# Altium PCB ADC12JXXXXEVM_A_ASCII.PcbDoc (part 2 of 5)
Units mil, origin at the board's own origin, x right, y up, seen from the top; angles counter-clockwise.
Board outline 5739 x 2680 mil, 10 copper layers (Top Layer L1, Gnd-Plane - L2, Signals - L3, Gnd-Plane - L4, Pwr Plane - L5, Signals - L6, Gnd-Plane - L7, Signals - L8, Gnd-Plane - L9, Bottom Layer - L10), stack 57.8 mil thick; 582 components, 343 nets, 1924 pads, 1318 vias.
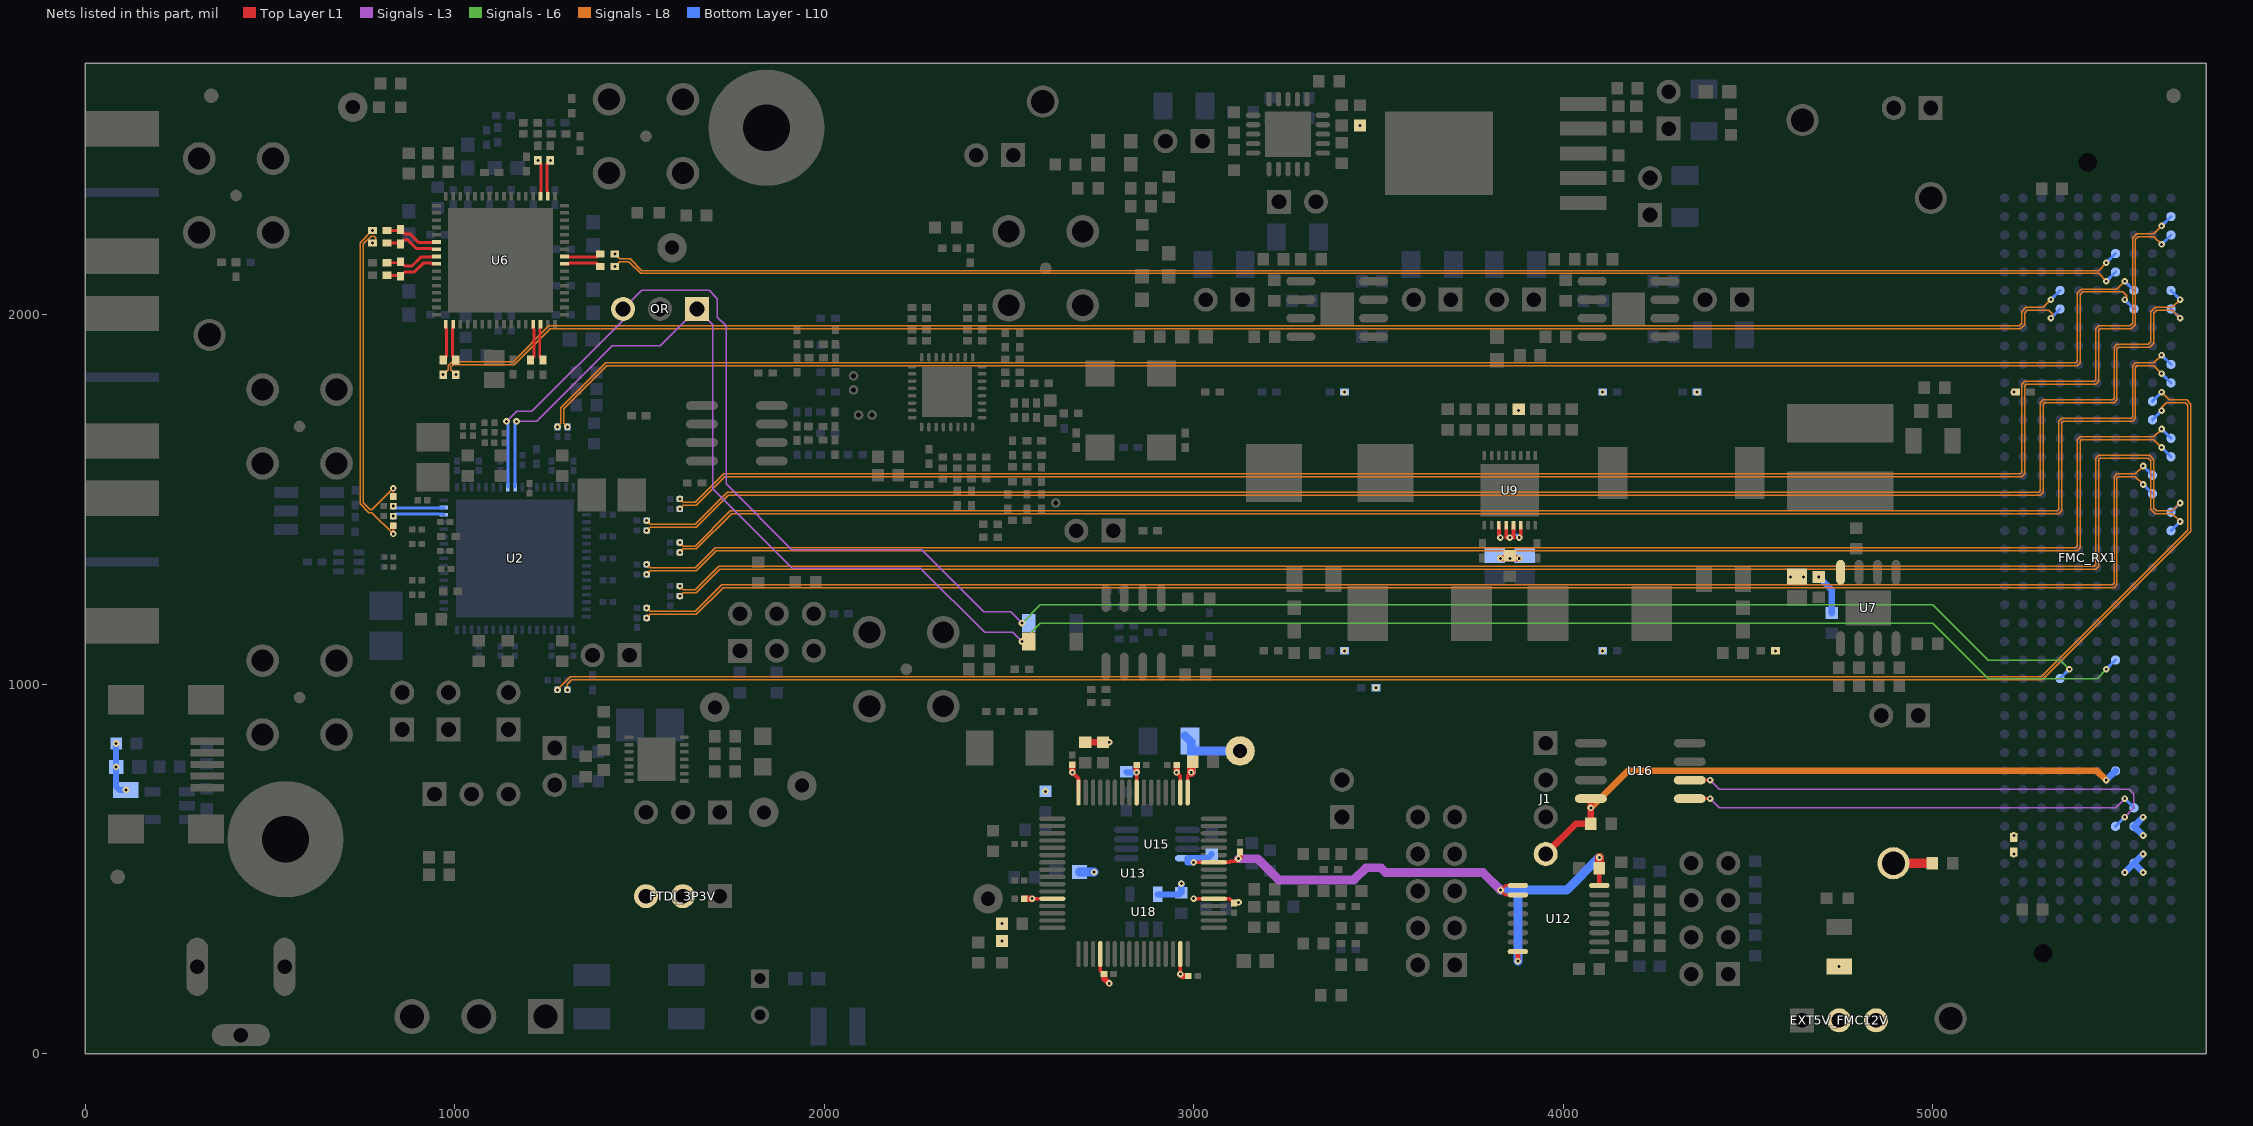
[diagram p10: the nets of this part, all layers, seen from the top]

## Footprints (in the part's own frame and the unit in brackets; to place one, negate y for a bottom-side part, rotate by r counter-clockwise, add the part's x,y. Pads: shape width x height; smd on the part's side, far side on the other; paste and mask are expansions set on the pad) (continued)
CONN_SEARAY_ASP-134488-01 [mm]
  round 0.635 hole 1.27 unplated mask+0.572: 401(27.191,0) 402(-27.191,-3.048)
  round 0.64 smd paste+0.125 mask+0.05: A1(24.716,5.715) A2(23.446,5.715) A3(22.176,5.715) A4(20.906,5.715) A5(19.636,5.715) A6(18.366,5.715) A7(17.096,5.715) A8(15.826,5.715) A9(14.556,5.715) A10(13.286,5.715) A11(12.016,5.715) A12(10.746,5.715) A13(9.476,5.715) A14(8.206,5.715) A15(6.936,5.715) A16(5.666,5.715) A17(4.396,5.715) A18(3.126,5.715) A19(1.856,5.715) A20(0.586,5.715) A21(-0.684,5.715) A22(-1.954,5.715) A23(-3.224,5.715) A24(-4.494,5.715) A25(-5.764,5.715) A26(-7.034,5.715) A27(-8.304,5.715) A28(-9.574,5.715) A29(-10.844,5.715) A30(-12.114,5.715) A31(-13.384,5.715) A32(-14.654,5.715) A33(-15.924,5.715) A34(-17.194,5.715) A35(-18.464,5.715) A36(-19.734,5.715) A37(-21.004,5.715) A38(-22.274,5.715) A39(-23.544,5.715) A40(-24.814,5.715) B1(24.716,4.445) B2(23.446,4.445) B3(22.176,4.445) B4(20.906,4.445) B5(19.636,4.445) B6(18.366,4.445) B7(17.096,4.445) B8(15.826,4.445) B9(14.556,4.445) B10(13.286,4.445) B11(12.016,4.445) B12(10.746,4.445) B13(9.476,4.445) B14(8.206,4.445) B15(6.936,4.445) B16(5.666,4.445) B17(4.396,4.445) B18(3.126,4.445) B19(1.856,4.445) B20(0.586,4.445) B21(-0.684,4.445) B22(-1.954,4.445) B23(-3.224,4.445) B24(-4.494,4.445) B25(-5.764,4.445) B26(-7.034,4.445) B27(-8.304,4.445) B28(-9.574,4.445) B29(-10.844,4.445) B30(-12.114,4.445) B31(-13.384,4.445) B32(-14.654,4.445) B33(-15.924,4.445) B34(-17.194,4.445) B35(-18.464,4.445) B36(-19.734,4.445) B37(-21.004,4.445) B38(-22.274,4.445) B39(-23.544,4.445) B40(-24.814,4.445) C1(24.716,3.175) C2(23.446,3.175) C3(22.176,3.175) C4(20.906,3.175) C5(19.636,3.175) C6(18.366,3.175) C7(17.096,3.175) C8(15.826,3.175) C9(14.556,3.175) C10(13.286,3.175) C11(12.016,3.175) C12(10.746,3.175) C13(9.476,3.175) C14(8.206,3.175) C15(6.936,3.175) C16(5.666,3.175) C17(4.396,3.175) C18(3.126,3.175) C19(1.856,3.175) C20(0.586,3.175) C21(-0.684,3.175) C22(-1.954,3.175) C23(-3.224,3.175) C24(-4.494,3.175) C25(-5.764,3.175) C26(-7.034,3.175) C27(-8.304,3.175) C28(-9.574,3.175) C29(-10.844,3.175) C30(-12.114,3.175) C31(-13.384,3.175) C32(-14.654,3.175) C33(-15.924,3.175) C34(-17.194,3.175) C35(-18.464,3.175) C36(-19.734,3.175) C37(-21.004,3.175) C38(-22.274,3.175) C39(-23.544,3.175) C40(-24.814,3.175) D1(24.716,1.905) D2(23.446,1.905) D3(22.176,1.905) D4(20.906,1.905) D5(19.636,1.905) D6(18.366,1.905) D7(17.096,1.905) D8(15.826,1.905) D9(14.556,1.905) D10(13.286,1.905) D11(12.016,1.905) D12(10.746,1.905) D13(9.476,1.905) D14(8.206,1.905) D15(6.936,1.905) D16(5.666,1.905) D17(4.396,1.905) D18(3.126,1.905) D19(1.856,1.905) D20(0.586,1.905) D21(-0.684,1.905) D22(-1.954,1.905) D23(-3.224,1.905) D24(-4.494,1.905) D25(-5.764,1.905) D26(-7.034,1.905) D27(-8.304,1.905) D28(-9.574,1.905) D29(-10.844,1.905) D30(-12.114,1.905) D31(-13.384,1.905) D32(-14.654,1.905) D33(-15.924,1.905) D34(-17.194,1.905) D35(-18.464,1.905) D36(-19.734,1.905) D37(-21.004,1.905) D38(-22.274,1.905) D39(-23.544,1.905) D40(-24.814,1.905) E1(24.716,0.635) E2(23.446,0.635) E3(22.176,0.635) E4(20.906,0.635) E5(19.636,0.635) E6(18.366,0.635) E7(17.096,0.635) E8(15.826,0.635) E9(14.556,0.635) E10(13.286,0.635) E11(12.016,0.635) E12(10.746,0.635) E13(9.476,0.635) E14(8.206,0.635) E15(6.936,0.635) E16(5.666,0.635) E17(4.396,0.635) E18(3.126,0.635) E19(1.856,0.635) E20(0.586,0.635) E21(-0.684,0.635) E22(-1.954,0.635) E23(-3.224,0.635) E24(-4.494,0.635) E25(-5.764,0.635) E26(-7.034,0.635) E27(-8.304,0.635) E28(-9.574,0.635) E29(-10.844,0.635) E30(-12.114,0.635) E31(-13.384,0.635) E32(-14.654,0.635) E33(-15.924,0.635) E34(-17.194,0.635) E35(-18.464,0.635) E36(-19.734,0.635) E37(-21.004,0.635) E38(-22.274,0.635) E39(-23.544,0.635) E40(-24.814,0.635) F1(24.716,-0.635) F2(23.446,-0.635) F3(22.176,-0.635) F4(20.906,-0.635) F5(19.636,-0.635) F6(18.366,-0.635) F7(17.096,-0.635) F8(15.826,-0.635) F9(14.556,-0.635) F10(13.286,-0.635) F11(12.016,-0.635) F12(10.746,-0.635) F13(9.476,-0.635) F14(8.206,-0.635) F15(6.936,-0.635) F16(5.666,-0.635) F17(4.396,-0.635) F18(3.126,-0.635) F19(1.856,-0.635) F20(0.586,-0.635) F21(-0.684,-0.635) F22(-1.954,-0.635) F23(-3.224,-0.635) F24(-4.494,-0.635) F25(-5.764,-0.635) F26(-7.034,-0.635) F27(-8.304,-0.635) F28(-9.574,-0.635) F29(-10.844,-0.635) F30(-12.114,-0.635) F31(-13.384,-0.635) F32(-14.654,-0.635) F33(-15.924,-0.635) F34(-17.194,-0.635) F35(-18.464,-0.635) F36(-19.734,-0.635) F37(-21.004,-0.635) F38(-22.274,-0.635) F39(-23.544,-0.635) F40(-24.814,-0.635) G1(24.716,-1.905) G2(23.446,-1.905) G3(22.176,-1.905) G4(20.906,-1.905) G5(19.636,-1.905) G6(18.366,-1.905) G7(17.096,-1.905) G8(15.826,-1.905) G9(14.556,-1.905) G10(13.286,-1.905) G11(12.016,-1.905) G12(10.746,-1.905) G13(9.476,-1.905) G14(8.206,-1.905) G15(6.936,-1.905) G16(5.666,-1.905) G17(4.396,-1.905) G18(3.126,-1.905) G19(1.856,-1.905) G20(0.586,-1.905) G21(-0.684,-1.905) G22(-1.954,-1.905) G23(-3.224,-1.905) G24(-4.494,-1.905) G25(-5.764,-1.905) G26(-7.034,-1.905) G27(-8.304,-1.905) G28(-9.574,-1.905) G29(-10.844,-1.905) G30(-12.114,-1.905) G31(-13.384,-1.905) G32(-14.654,-1.905) G33(-15.924,-1.905) G34(-17.194,-1.905) G35(-18.464,-1.905) G36(-19.734,-1.905) G37(-21.004,-1.905) G38(-22.274,-1.905) G39(-23.544,-1.905) G40(-24.814,-1.905) H1(24.716,-3.175) H2(23.446,-3.175) H3(22.176,-3.175) H4(20.906,-3.175) H5(19.636,-3.175) H6(18.366,-3.175) H7(17.096,-3.175) H8(15.826,-3.175) H9(14.556,-3.175) H10(13.286,-3.175) H11(12.016,-3.175) H12(10.746,-3.175) H13(9.476,-3.175) H14(8.206,-3.175) H15(6.936,-3.175) H16(5.666,-3.175) H17(4.396,-3.175) H18(3.126,-3.175) H19(1.856,-3.175) H20(0.586,-3.175) H21(-0.684,-3.175) H22(-1.954,-3.175) H23(-3.224,-3.175) H24(-4.494,-3.175) H25(-5.764,-3.175) H26(-7.034,-3.175) H27(-8.304,-3.175) H28(-9.574,-3.175) H29(-10.844,-3.175) H30(-12.114,-3.175) H31(-13.384,-3.175) H32(-14.654,-3.175) H33(-15.924,-3.175) H34(-17.194,-3.175) H35(-18.464,-3.175) H36(-19.734,-3.175) H37(-21.004,-3.175) H38(-22.274,-3.175) H39(-23.544,-3.175) H40(-24.814,-3.175) J1(24.716,-4.445) J2(23.446,-4.445) J3(22.176,-4.445) J4(20.906,-4.445) J5(19.636,-4.445) J6(18.366,-4.445) J7(17.096,-4.445) J8(15.826,-4.445) J9(14.556,-4.445) J10(13.286,-4.445) J11(12.016,-4.445) J12(10.746,-4.445) J13(9.476,-4.445) J14(8.206,-4.445) J15(6.936,-4.445) J16(5.666,-4.445) J17(4.396,-4.445) J18(3.126,-4.445) J19(1.856,-4.445) J20(0.586,-4.445) J21(-0.684,-4.445) J22(-1.954,-4.445) J23(-3.224,-4.445) J24(-4.494,-4.445) J25(-5.764,-4.445) J26(-7.034,-4.445) J27(-8.304,-4.445) J28(-9.574,-4.445) J29(-10.844,-4.445) J30(-12.114,-4.445) J31(-13.384,-4.445) J32(-14.654,-4.445) J33(-15.924,-4.445) J34(-17.194,-4.445) J35(-18.464,-4.445) J36(-19.734,-4.445) J37(-21.004,-4.445) J38(-22.274,-4.445) J39(-23.544,-4.445) J40(-24.814,-4.445) K1(24.716,-5.715) K2(23.446,-5.715) K3(22.176,-5.715) K4(20.906,-5.715) K5(19.636,-5.715) K6(18.366,-5.715) K7(17.096,-5.715) K8(15.826,-5.715) K9(14.556,-5.715) K10(13.286,-5.715) K11(12.016,-5.715) K12(10.746,-5.715) K13(9.476,-5.715) K14(8.206,-5.715) K15(6.936,-5.715) K16(5.666,-5.715) K17(4.396,-5.715) K18(3.126,-5.715) K19(1.856,-5.715) K20(0.586,-5.715) K21(-0.684,-5.715) K22(-1.954,-5.715) K23(-3.224,-5.715) K24(-4.494,-5.715) K25(-5.764,-5.715) K26(-7.034,-5.715) K27(-8.304,-5.715) K28(-9.574,-5.715) K29(-10.844,-5.715) K30(-12.114,-5.715) K31(-13.384,-5.715) K32(-14.654,-5.715) K33(-15.924,-5.715) K34(-17.194,-5.715) K35(-18.464,-5.715) K36(-19.734,-5.715) K37(-21.004,-5.715) K38(-22.274,-5.715) K39(-23.544,-5.715) K40(-24.814,-5.715)
  silkscreen extent -28.49,-8.18 29.69,8.18, body extent -27.89,-7.34 29.49,7.34, height 7.07
CONN_USB-MINI-AB-651-305-142-821 [mm] "WE-USB2-MINI-AB TYPE"
  rect 0.5x2.3 smd: 1(-1.6,2.8) 2(-0.8,2.8) 3(0,2.8) 4(0.8,2.8) 5(1.6,2.8)
  rect 2x2.5 smd: 6(4.45,2.7) 7(4.45,-2.8) 8(-4.45,-2.8) 9(-4.45,2.7)
  silkscreen extent -4.03,-5.6 4,1.1, body extent -4.95,-5.72 4.95,3.68, height 4.12
DBV0005A_N [mm] "SOT23, 5-Leads, Body 2.9x1.6mm, Pitch 0.95mm, Lead Span 2.8mm, IPC Medium Density"
  rect 1.1x0.65 smd: 1(-1.2,0.95) 2(-1.2,0) 3(-1.2,-0.95) 4(1.2,-0.95) 5(1.2,0.95)
  silkscreen extent -1.33,-1.55 0.25,1.95, body extent -0.87,-1.52 0.87,1.53, height 1.45
DDA0008B_L [mm] "SOIC, 8-Leads, Body 4.9x3.9mm, Pitch 1.27mm, Exposed Pad, IPC High Density"
  oval 1.7x0.6 smd: 1(-2.45,1.905) 2(-2.45,0.635) 3(-2.45,-0.635) 4(-2.45,-1.905) 5(2.45,-1.905) 6(2.45,-0.635) 7(2.45,0.635) 8(2.45,1.905)
  rect 2.41x3.1 smd: 9(0,0)
  silkscreen extent -2.57,-2.5 1.2,2.88, body extent -2,-2.5 2,2.5, height 1.68
ESD_Overlay_Small [mil]
  silkscreen extent -62,-48 64,61
Fiducial10-30 [mm]
  round 1 smd paste-0.5 mask+1: 1(0,0)
  Keep-Out Layer circle w1.678: c0,0 r0.75
IND_TDK_ACM7060 [mm] "TDK Common Mode EMI Filter 7mmx6mm"
  rect 2.5x1.5 smd: 1(-3.25,1.5) 2(-3.25,-1.5) 3(3.25,-1.5) 4(3.25,1.5)
  silkscreen extent -4.8,-3.32 4.75,3.31, body extent -3.6,-3.12 3.6,3.07, height 3.55
Johnson_142-0701-80x [mil] "Johnson Components recommended land pattern"
  rect 25x200 smd: 1(0,0)
  rect 95x200 smd: 2(-172.5,0) 3(172.5,0)
  rect 95x200 smd far side: 4(-172.5,0) 5(172.5,0)
  silkscreen extent -235,-170 235,100, body extent -190,-92 190,480, height 165
Keystone5011 [mil] "Keystone Multipurpose loops"
  round 87 hole 63: 1(0,0)
  silkscreen extent -70,-70 70,70, body extent -63,-63 63,62, height 319
Keystone_1902C [mil] "Hex Standoff, 4-40 threaded, nylon"
  round 1 on Mech4: 0(0,0)
  body extent -145,-126 146,126, height 501
Label_650x200 [mil] "Thermal Transfer Label"
  silkscreen extent -325,-100 325,100, body extent -326,-101 326,101, height 1
LED_LTST-C170 [mm] "LITE-ON"
  rect 1.2x1.2 smd: 1(-1.05,0) 2(1.05,0)
  silkscreen extent -1.6,-1.1 3,1.1, body extent -1.05,-0.67 1.05,0.67, height 1.1
LED_LTST-C190 [mm] "Lite-On"
  rect 0.8x0.8 smd: 1(-0.75,0) 2(0.75,0)
  silkscreen extent -1.1,-0.8 1.8,0.8, body extent -0.85,-0.45 0.85,0.45, height 0.9
LQFP64_N [mm] "Thin QFP, 64-Leads, Body 10x10mm, Pitch 0.5mm, IPC Medium Density"
  oval 1.8x0.3 smd mask+0.049: 1(-5.55,3.75) 2(-5.55,3.25) 3(-5.55,2.75) 4(-5.55,2.25) 5(-5.55,1.75) 6(-5.55,1.25) 7(-5.55,0.75) 8(-5.55,0.25) 9(-5.55,-0.25) 10(-5.55,-0.75) 11(-5.55,-1.25) 12(-5.55,-1.75) 13(-5.55,-2.25) 14(-5.55,-2.75) 15(-5.55,-3.25) 16(-5.55,-3.75) 33(5.55,-3.75) 34(5.55,-3.25) 35(5.55,-2.75) 36(5.55,-2.25) 37(5.55,-1.75) 38(5.55,-1.25) 39(5.55,-0.75) 40(5.55,-0.25) 41(5.55,0.25) 42(5.55,0.75) 43(5.55,1.25) 44(5.55,1.75) 45(5.55,2.25) 46(5.55,2.75) 47(5.55,3.25) 48(5.55,3.75)
  oval 0.3x1.8 smd mask+0.049: 17(-3.75,-5.55) 18(-3.25,-5.55) 19(-2.75,-5.55) 20(-2.25,-5.55) 21(-1.75,-5.55) 22(-1.25,-5.55) 23(-0.75,-5.55) 24(-0.25,-5.55) 25(0.25,-5.55) 26(0.75,-5.55) 27(1.25,-5.55) 28(1.75,-5.55) 29(2.25,-5.55) 30(2.75,-5.55) 31(3.25,-5.55) 32(3.75,-5.55) 49(3.75,5.55) 50(3.25,5.55) 51(2.75,5.55) 52(2.25,5.55) 53(1.75,5.55) 54(1.25,5.55) 55(0.75,5.55) 56(0.25,5.55) 57(-0.25,5.55) 58(-0.75,5.55) 59(-1.25,5.55) 60(-1.75,5.55) 61(-2.25,5.55) 62(-2.75,5.55) 63(-3.25,5.55) 64(-3.75,5.55)
  silkscreen extent -5.67,-4.25 4.25,4.57, body extent -5,-5 5,5, height 1.6
M08A_L [mm] "SOIC, 8-Leads, Body 4.9x3.9mm, Pitch 1.27mm, IPC High Density"
  oval 1.9x0.6 smd: 1(-2.35,1.905) 2(-2.35,0.635) 3(-2.35,-0.635) 4(-2.35,-1.905) 5(2.35,-1.905) 6(2.35,-0.635) 7(2.35,0.635) 8(2.35,1.905)
  silkscreen extent -2.47,-2.5 1,2.88, body extent -2,-2.5 2,2.5, height 1.75
Mini-Circuits-DB1627 [mm] "Mini-Circuits DB1627 Footprint"
  rect 0.76x1.65 smd: 1(-1.27,1.59) 2(0,1.59) 3(1.27,1.59) 4(1.27,-1.59) 5(0,-1.59) 6(-1.27,-1.59)
  silkscreen extent -3.01,-2.03 1.91,2.03, body extent -1.91,-2.03 1.91,2.03, height 4.07
MRA08A_N [mm] "SOIC, 8-Leads, Body 4.9x3.9mm, Pitch 1.27mm, Exposed Pad, IPC Medium Density"
  oval 2x0.6 smd: 1(-2.5,1.905) 2(-2.5,0.635) 3(-2.5,-0.635) 4(-2.5,-1.905) 5(2.5,-1.905) 6(2.5,-0.635) 7(2.5,0.635) 8(2.5,1.905)
  rect 2.29x2.29 smd: 9(0,0)
  silkscreen extent -2.63,-2.5 1.1,2.88, body extent -2,-2.5 2,2.5, height 1.68
MSOP-MS8_N [mm] "TSOP, 8-Leads, Body 3x3mm, Pitch 0.65mm, IPC Medium Density"
  oval 1.7x0.45 smd mask+0.049: 1(-2.1,0.975) 2(-2.1,0.325) 3(-2.1,-0.325) 4(-2.1,-0.975) 5(2.1,-0.975) 6(2.1,-0.325) 7(2.1,0.325) 8(2.1,0.975)
  silkscreen extent -2.22,-1.55 0.85,1.87, body extent -1.6,-1.6 1.6,1.6, height 1.1
MSS1038 [mil]
  rect 80x140 smd: 1(-185,0) 2(185,0)
  silkscreen extent -216,-208 215,208, body extent -203,-201 203,201, height 158
NKD0064A [mm] "QFN, 64-Leads, Body 9x9mm, Pitch 0.5mm"
  rect 0.6x0.25 smd mask+0.051: 1(-4.4,3.75) 2(-4.4,3.25) 3(-4.4,2.75) 4(-4.4,2.25) 5(-4.4,1.75) 6(-4.4,1.25) 7(-4.4,0.75) 8(-4.4,0.25) 9(-4.4,-0.25) 10(-4.4,-0.75) 11(-4.4,-1.25) 12(-4.4,-1.75) 13(-4.4,-2.25) 14(-4.4,-2.75) 15(-4.4,-3.25) 16(-4.4,-3.75) 33(4.4,-3.75) 34(4.4,-3.25) 35(4.4,-2.75) 36(4.4,-2.25) 37(4.4,-1.75) 38(4.4,-1.25) 39(4.4,-0.75) 40(4.4,-0.25) 41(4.4,0.25) 42(4.4,0.75) 43(4.4,1.25) 44(4.4,1.75) 45(4.4,2.25) 46(4.4,2.75) 47(4.4,3.25) 48(4.4,3.75)
  rect 0.25x0.6 smd mask+0.051: 17(-3.75,-4.4) 18(-3.25,-4.4) 19(-2.75,-4.4) 20(-2.25,-4.4) 21(-1.75,-4.4) 22(-1.25,-4.4) 23(-0.75,-4.4) 24(-0.25,-4.4) 25(0.25,-4.4) 26(0.75,-4.4) 27(1.25,-4.4) 28(1.75,-4.4) 29(2.25,-4.4) 30(2.75,-4.4) 31(3.25,-4.4) 32(3.75,-4.4) 49(3.75,4.4) 50(3.25,4.4) 51(2.75,4.4) 52(2.25,4.4) 53(1.75,4.4) 54(1.25,4.4) 55(0.75,4.4) 56(0.25,4.4) 57(-0.25,4.4) 58(-0.75,4.4) 59(-1.25,4.4) 60(-1.75,4.4) 61(-2.25,4.4) 62(-2.75,4.4) 63(-3.25,4.4) 64(-3.75,4.4)
  rect 7.2x7.2 smd paste-3.6 mask+0.051: 65(0,0)
  silkscreen extent -5.52,-4.85 4.85,4.85, body extent -4.55,-4.55 4.55,4.55, height 0.8
"NY PMS 440 0025 PH"#1 [mm] "4-40 nylon screw and mounting hole"
  round 8 / inner round 4.216 / far side round 8 hole 3.2 mask+0.037: 1(0,0)
  body extent -3.3,-3.3 3.3,3.3, height 2.69
"NY PMS 440 0025 PH"#2 [mm] "4-40 nylon screw and mounting hole"
  round 8 / inner round 4.216 / far side round 8 hole 3.2: 1(0,0)
  body extent -3.3,-3.3 3.3,3.3, height 2.69
OSC_CWX [mm] "CONNOR WINFIELD"
  rect 2x1.8 smd: 1(-2.1,2.54) 2(-2.1,-2.54) 3(2.1,-2.54) 4(2.1,2.54)
  silkscreen extent -2.7,-3.7 2.7,4.55, body extent -2.65,-3.65 2.65,3.65, height 1.31
PBC03SAAN [mm] "Sullins 100mil, 1x3, 230 mil above insulator"
  rect 1.65x1.65 hole 1.016: 1(-2.54,0)
  round 1.65 hole 1.016: 2(0,0) 3(2.54,0)
  silkscreen extent -3.81,-1.27 3.81,1.27, body extent -3.81,-1.27 3.81,1.27, height 8.38
PW0016A_L [mm] "TSOP, 16-Leads, Body 5x4.4mm, Pitch 0.65mm, IPC High Density"
  oval 1.4x0.35 smd: 1(-2.8,2.275) 2(-2.8,1.625) 3(-2.8,0.975) 4(-2.8,0.325) 5(-2.8,-0.325) 6(-2.8,-0.975) 7(-2.8,-1.625) 8(-2.8,-2.275) 9(2.8,-2.275) 10(2.8,-1.625) 11(2.8,-0.975) 12(2.8,-0.325) 13(2.8,0.325) 14(2.8,0.975) 15(2.8,1.625) 16(2.8,2.275)
  silkscreen extent -2.92,-2.55 1.7,3.12, body extent -2.25,-2.55 2.25,2.55, height 1.2
RGW0020A [mm] "QFN, 20-Leads, Body 5x5mm, Pitch 0.65mm, Thermal Pad 3.15x3.15mm, TI Recommended"
  oval 1x0.35 smd paste-0.025 mask+0.07: 1(-2.4,1.3) 2(-2.4,0.65) 3(-2.4,0) 4(-2.4,-0.65) 5(-2.4,-1.3) 11(2.4,-1.3) 12(2.4,-0.65) 13(2.4,0) 14(2.4,0.65) 15(2.4,1.3)
  oval 0.35x1 smd paste-0.025 mask+0.07: 6(-1.3,-2.4) 7(-0.65,-2.4) 8(0,-2.4) 9(0.65,-2.4) 10(1.3,-2.4) 16(1.3,2.4) 17(0.65,2.4) 18(0,2.4) 19(-0.65,2.4) 20(-1.3,2.4)
  rect 3.15x3.15 smd paste-1.575 mask+0.07: 21(0,0)
  silkscreen extent -3.5,-2.73 2.73,2.73, body extent -2.58,-2.57 2.57,2.58, height 1
RHB0032E [mm] "QFN, 32-Leads, Body 5x5mm, Pitch 0.5mm, Thermal Pad 3.45x3.45mm, TI Recommended"
  oval 0.6x0.24 smd mask+0.07: 1(-2.4,1.75) 2(-2.4,1.25) 3(-2.4,0.75) 4(-2.4,0.25) 5(-2.4,-0.25) 6(-2.4,-0.75) 7(-2.4,-1.25) 8(-2.4,-1.75) 17(2.4,-1.75) 18(2.4,-1.25) 19(2.4,-0.75) 20(2.4,-0.25) 21(2.4,0.25) 22(2.4,0.75) 23(2.4,1.25) 24(2.4,1.75)
  oval 0.24x0.6 smd mask+0.07: 9(-1.75,-2.4) 10(-1.25,-2.4) 11(-0.75,-2.4) 12(-0.25,-2.4) 13(0.25,-2.4) 14(0.75,-2.4) 15(1.25,-2.4) 16(1.75,-2.4) 25(1.75,2.4) 26(1.25,2.4) 27(0.75,2.4) 28(0.25,2.4) 29(-0.25,2.4) 30(-0.75,2.4) 31(-1.25,2.4) 32(-1.75,2.4)
  rect 3.45x3.45 smd paste-1.725 mask+0.07: 33(0,0)
  silkscreen extent -2.72,2.29 -2.29,2.73, body extent -2.57,-2.57 2.58,2.58, height 1.01
RLY0068A [mm] "QFN, 68-Leads, Body 10x10mm, Pitch 0.5mm"
  rect 0.6x0.25 smd mask+0.051: 1(-4.9,4) 2(-4.9,3.5) 3(-4.9,3) 4(-4.9,2.5) 5(-4.9,2) 6(-4.9,1.5) 7(-4.9,1) 8(-4.9,0.5) 9(-4.9,0) 10(-4.9,-0.5) 11(-4.9,-1) 12(-4.9,-1.5) 13(-4.9,-2) 14(-4.9,-2.5) 15(-4.9,-3) 16(-4.9,-3.5) 17(-4.9,-4) 35(4.9,-4) 36(4.9,-3.5) 37(4.9,-3) 38(4.9,-2.5) 39(4.9,-2) 40(4.9,-1.5) 41(4.9,-1) 42(4.9,-0.5) 43(4.9,0) 44(4.9,0.5) 45(4.9,1) 46(4.9,1.5) 47(4.9,2) 48(4.9,2.5) 49(4.9,3) 50(4.9,3.5) 51(4.9,4)
  rect 0.25x0.6 smd mask+0.051: 18(-4,-4.9) 19(-3.5,-4.9) 20(-3,-4.9) 21(-2.5,-4.9) 22(-2,-4.9) 23(-1.5,-4.9) 24(-1,-4.9) 25(-0.5,-4.9) 26(0,-4.9) 27(0.5,-4.9) 28(1,-4.9) 29(1.5,-4.9) 30(2,-4.9) 31(2.5,-4.9) 32(3,-4.9) 33(3.5,-4.9) 34(4,-4.9) 52(4,4.9) 53(3.5,4.9) 54(3,4.9) 55(2.5,4.9) 56(2,4.9) 57(1.5,4.9) 58(1,4.9) 59(0.5,4.9) 60(0,4.9) 61(-0.5,4.9) 62(-1,4.9) 63(-1.5,4.9) 64(-2,4.9) 65(-2.5,4.9) 66(-3,4.9) 67(-3.5,4.9) 68(-4,4.9)
  rect 8.1x8.1 smd paste-4.05 mask+0.051: 69(0,0)
  silkscreen extent -5.87,-5.2 5.2,5.2, body extent -5.05,-5.05 5.05,5.05, height 1.01
SDA14B [mm] "SON, 14-Leads, Body 4x4mm, Pitch 0.5mm, NSC Recommended"
  rect 0.6x0.25 smd paste-0.125 mask+0.051: 1(-1.9,1.5) 2(-1.9,1) 3(-1.9,0.5) 4(-1.9,0) 5(-1.9,-0.5) 6(-1.9,-1) 7(-1.9,-1.5) 8(1.9,-1.5) 9(1.9,-1) 10(1.9,-0.5) 11(1.9,0) 12(1.9,0.5) 13(1.9,1) 14(1.9,1.5)
  rect 2.6x3 smd paste-1.3 mask+0.051: 15(0,0)
  silkscreen extent -2.82,-2.2 2.35,2.87, body extent -2.05,-2.05 2.05,2.05, height 0.8
SDA16A [mm] "SON, 16-Leads, Body 5x5mm, Pitch 0.5mm, NSC Recommended"
  rect 0.6x0.25 smd paste-0.125 mask+0.051: 1(-2.4,1.75) 2(-2.4,1.25) 3(-2.4,0.75) 4(-2.4,0.25) 5(-2.4,-0.25) 6(-2.4,-0.75) 7(-2.4,-1.25) 8(-2.4,-1.75) 9(2.4,-1.75) 10(2.4,-1.25) 11(2.4,-0.75) 12(2.4,-0.25) 13(2.4,0.25) 14(2.4,0.75) 15(2.4,1.25) 16(2.4,1.75)
  rect 3.6x4 smd paste-1.8 mask+0.051: 17(0,0)
  silkscreen extent -2.85,-2.7 2.85,3.53, body extent -2.55,-2.55 2.55,2.55, height 0.8
SMC [mil] "Molded Diode, 2-Leads, Body 6.9x5.8mm, IPC Medium Density, based on OnSemi component dimensions and land patterns"
  rect 110x150 smd: 1(-140.49,0) 2(140.49,0)
  silkscreen extent -221,-124 189,124, body extent -156,-116 156,116, height 91
SNT-100-BK-G [mil] "Samtec STEP model"
  round 1 on Mech3: 0(0,0)
  body extent -100,-50 100,50, height 344
SOD-123 [mm] "On Semi recommended land pattern"
  rect 0.915x1.22 smd: 1(-1.637,0) 2(1.637,0)
  silkscreen extent -2.74,-1.17 2.03,1.17, body extent -1.93,-0.9 1.93,0.9, height 1.35
SOIJ-SM8_N [mm] "SOP, 8-Leads, Body 5.2x5.2mm, Pitch 1.27mm, IPC Medium Density"
  oval 2.2x0.6 smd: 1(-3.4,1.905) 2(-3.4,0.635) 3(-3.4,-0.635) 4(-3.4,-1.905) 5(3.4,-1.905) 6(3.4,-0.635) 7(3.4,0.635) 8(3.4,1.905)
  silkscreen extent -3.52,-2.75 1.9,2.88, body extent -2.73,-2.75 2.73,2.75, height 2.04
SOP-5_.95MM_(DBV) [mil]
  rect 42x25 smd: 1(-48.94,37.39) 2(-48.94,0) 3(-48.94,-37.39) 4(45.94,-37.39) 5(45.94,37.39)
  silkscreen extent -109,25 -84,50
"SW_ L101011MS02Q" [mm] "SWITCH SLIDE sPST 4A PCB"
  rect 2.416x2.416 hole 1.65: 1(2.855,4.6)
  round 2.416 hole 1.65: 2(2.855,0) 3(2.855,-4.6)
  silkscreen extent -5.4,-9.55 5.4,9.55, body extent -5.39,-9.55 5.39,9.55, height 14.18
TESTPOINT#1 [mil]
  round 80 hole 37.99: 1(0,0)
TESTPOINT#2 [mil]
  round 25.98 hole 12.99: 1(0,0)
TESTPOINT#3 [mil]
  round 25.98 hole 12.99: 1(0,23.68)
TI_Symbol_Overlay_Small [mil]
  silkscreen extent -90,-88 91,88
TJ5A_N [mm] "D2-PAK, 6-Leads, Body 9.9x10.2mm, Pitch 1.7mm, Lead Span 14mm, IPC Medium Density"
  rect 3.2x0.95 smd: 1(-6,3.4) 2(-6,1.7) 3(-6,0) 4(-6,-1.7) 5(-6,-3.4)
  rect 7.4x5.75 smd: 6(3.9,0)
  silkscreen extent -6.12,-5.2 -0.2,5.2, body extent -1.95,-5.2 8.15,5.2, height 2.1
TSW-102-07-G-S [mm] "Samtec 100mil, 1x2, 230 mil above insulator"
  rect 1.65x1.65 hole 1.016 mask+0: 1(-1.27,0)
  round 1.65 hole 1.016 mask+0: 2(1.27,0)
  silkscreen extent -3.56,-1.27 2.54,1.27, body extent -2.54,-1.27 2.54,1.27, height 8.38
TSW-103-07-G-D [mm] "Samtec 100mil, 2x3, 230 mil above insulator"
  rect 1.65x1.65 hole 1.016 mask+0: 1(-2.54,-1.27)
  round 1.65 hole 1.016 mask+0: 2(-2.54,1.27) 3(0,-1.27) 4(0,1.27) 5(2.54,-1.27) 6(2.54,1.27)
  silkscreen extent -4.83,-2.54 3.81,2.54, body extent -3.81,-2.54 3.81,2.54, height 8.38
TSW-103-07-G-S [mm] "Samtec 100mil, 1x3, 230 mil above insulator"
  rect 1.65x1.65 hole 1.016 mask+0: 1(-2.54,0)
  round 1.65 hole 1.016 mask+0: 2(0,0) 3(2.54,0)
  silkscreen extent -4.84,-1.27 3.81,1.27, body extent -3.81,-1.27 3.81,1.27, height 8.38
TSW-104-07-G-D [mm] "Samtec 100mil, 2x4, 230 mil above insulator"
  rect 1.65x1.65 hole 1.016 mask+0: 1(-3.81,-1.27)
  round 1.65 hole 1.016 mask+0: 2(-3.81,1.27) 3(-1.27,-1.27) 4(-1.27,1.27) 5(1.27,-1.27) 6(1.27,1.27) 7(3.81,-1.27) 8(3.81,1.27)
  silkscreen extent -6.1,-2.54 5.08,2.54, body extent -5.08,-2.54 5.08,2.54, height 8.38
TSW-104-07-G-S [mm] "Samtec 100mil, 1x4, 230 mil above insulator"
  rect 1.65x1.65 hole 1.016 mask+0: 1(-3.81,0)
  round 1.65 hole 1.016 mask+0: 2(-1.27,0) 3(1.27,0) 4(3.81,0)
  silkscreen extent -6.1,-1.27 5.08,1.27, body extent -5.08,-1.27 5.08,1.27, height 8.38
WE-HC6 [mm] "Wurth Electronik recommended land pattern"
  rect 3.85x4 smd: 1(-3.825,0) 2(3.825,0)
  silkscreen extent -6.2,-6.2 6.2,6.2, body extent -5.77,-5.37 5.75,5.35, height 5
XTAL_ABM3 [mm] "Abracon recommended land pattern 12.28.10"
  rect 1.9x2.4 smd: 1(-2.05,0) 2(2.05,0)
  silkscreen extent -2.67,-1.78 2.67,1.78, body extent -2.6,-1.7 2.6,1.7, height 1.3

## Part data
1P8USB 3P3USB LD1 LD2 LO2_N LO2_P LO3_N LO3_P TCRIT1 TCRIT2 TCRIT3 Vtune: "TEST POINT.  No entry in BOM."
1V2ADC_INT 1V2ADC_LDO 1V9ADC 1V9INT J2 J3 "KC705 JTAG" LMK_INT LMK_LDO LMX_INT LMX_LDO PG_RX1 Tdiode VA12 VA19 Vbg Vcmo VD12: "Header, TH, 100mil, 2x1, Gold plated, 230 mil above insulator"
3P3RX GND GND1 GND2 GND3 VADJ_RX: "Test Point, TH, Multipurpose, Black"
5VDC: "Connector, DC Jack 2.1X5.5 mm, TH"
12V LD Status1 Status2 USB_PWR: "LED, Green, SMD"
C1 C3 C5 C6: "CAP, CERM, 100pF, 16V, +/-10%, X7R, 0201"
C2 C8 C11 C94 C95 C96 C215 C216 C217 C218 C219 C220 C221 C222 C223 C224 C225 C226 C227 C261: "CAP, CERM, 0.1uF, 10V, +/-10%, X7R, 0402"
C4: "CAP, CERM, 10pF, 50V, +/-5%, C0G/NP0, 0402"
C7 C9 C10 C12 C13 C14 C15 C17 C20 C21 C22 C23 C26 C28 C29 C31 C41 C42 C43 C44 C45 C46 C47 C51 C52 C53 C54 C55 C56 C57 C58 C62 C63 C64 C65 C66 C67 C68 C69 C70 C71 C118 C119 C131 C132 C133 C134 C136 C140 C142 C214: library part Capacitor, "CAP, CERM, 0.1uF, 6.3V, X5R, 10%, 0201"
C16: "CAP, CERM, 4.7uF, 6.3V, +/-20%, X5R, 0402"
C18 C19 C73 C85 C86 C87 C88 C89 C103 C104 C105 C106 C107 C109 C110 C111 C112 C113 C114 C120 C121 C123 C124 C206 C207 C208 C209 C231 C235 C250 C251 C258 C259 C260: "CAP, CERM, 0.1uF, 10V, +/-10%, X5R, 0402"
C24 C115 C210: "CAP, CERM, 0.1uF, 16V, +/-5%, X7R, 0603"
C25 C34 C38: "CAP, CERM, 100pF, 50V, +/-5%, C0G/NP0, 0603"
C27 C48 C59 C72: "CAP, TANT, 10uF, 10V, +/-20%, 2.5 ohm, 3528-21 SMD"
C30 C36: "CAP, CERM, 0.22uF, 6.3V, +/-20%, X5R, 0201"
C32 C33 C35 C37 C90 C91 C92 C93 C262 C263: "CAP, CERM, 4700pF, 10V, +/-10%, X5R, 0201"
C39 C40 C49 C50 C60 C61 C125 C143 C205: "CAP, CERM, 1uF, 10V, +/-10%, X5R, 0603"
C74: "CAP, CERM, 100pF, 25V, +/-5%, C0G/NP0, 0402"
C75 C76 C83 C84 C245: "CAP, CERM, 47pF, 50V, +/-5%, C0G/NP0, 0402"
C77 C79 C239 C242 C253 C256: "CAP, CERM, 0.01uF, 25V, +/-10%, X7R, 0402"
C78 C80 C254 C257: "CAP, CERM, 27pF, 50V, +/-5%, C0G/NP0, 0402"
C81 C82 C232 C236 C240 C243 C252 C255: "CAP, CERM, 1uF, 6.3V, +/-20%, X5R, 0402"
C102: "CAP, CERM, 0.01uF, 16V, +/-10%, X7R, 0402"
C108 C155 C201 C211: "CAP, CERM, 1uF, 16V, +/-10%, X5R, 0603"
C116 C126 C129 C130 C144 C147 C148 C151 C153 C159 C164 C167 C176 C177 C185 C189 C191 C198 C199 C213: "CAP, CERM, 0.1uF, 25V, +/-5%, X7R, 0603"
C117 C149: "CAP, CERM, 330pF, 50V, +/-5%, C0G/NP0, 0603"
C122: "CAP, CERM, 10uF, 10V, +/-10%, X5R, 0805"
C127 C160: "CAP, CERM, 4.7uF, 10V, +/-10%, X5R, 0603"
C128 C161: "CAP, CERM, 0.01uF, 100V, +/-20%, X7R, 0603"
C135 C137: "CAP, CERM, 18pF, 50V, +/-5%, C0G/NP0, 0402"
C138 C212: "CAP, CERM, 100uF, 6.3V, +/-20%, X5R, 1206"
C139 C141 C150 C152 C158 C163 C165 C166 C171 C172 C186 C188 C190 C195 C196 C197 C200 C202 C203 C204: "CAP, CERM, 10uF, 10V, +/-10%, C0G/NP0, 0603"
C145 C146 C173 C184: "CAP, CERM, 10uF, 16V, +/-10%, X5R, 0805"
C154: "CAP, CERM, 10pF, 50V, +/-5%, C0G/NP0, 0603"
C156 C157: "CAP, CERM, 47uF, 6.3V, +/-20%, X5R, 1206"
C162: "CAP, CERM, 3300pF, 25V, +/-10%, X7R, 0603"
C168: "CAP, CERM, 0.22uF, 16V, +/-10%, X7R, 0603"
C169 C170: "CAP, CERM, 0.1uF, 6.3V, +/-10%, X5R, 0402"
C174 C175: "CAP, CERM, 0.027uF, 16V, +/-10%, X7R, 0603"
C178 C179: "CAP, CERM, 0.039uF, 25V, +/-10%, X7R, 0603"
C180 C181 C182 C183: "CAP, CERM, 22uF, 10V, +/-20%, X5R, 1206"
C187: "CAP, CERM, 560pF, 50V, +/-5%, C0G/NP0, 0603"
C192: "CAP, CERM, 4700pF, 16V, +/-10%, X7R, 0603"
C193: "CAP, AL, 100uF, 25V, +/-20%, TH"
C194: "CAP, CERM, 10uF, 25V, +/-10%, X6S, 1210"
C228 C229: library part GRM155R71A104KA01D, "CAP CER 0.5PF 50V NP0 0402"
C230 C234 LF2: "CAP, CERM, 47pF, 50V, +/-5%, C0G/NP0, 0603"
C233 C237 C238 C241 C246 C248: "CAP, CERM, 4.7pF, 50V, +/-5%, C0G/NP0, 0402"
C244: "CAP, CERM, 560pF, 50V, +/-5%, C0G/NP0, 0402"
C247: "CAP, CERM, 2.2pF, 50V, +/-5%, C0G/NP0, 0402"
C249: "CAP, CERM, 22pF, 50V, +/-5%, C0G/NP0, 0402"
D2 D4: "Diode, Ultrafast, 100V, 0.15A, SOD-123"
D11 D12: "Diode, Schottky, 40V, 5A, SMC"
DEVCLK EXT_VCO LMKCLK OSCin VIN+ VIN-: "Connector, SMA,Vertical, Thru hole w/SMT center pin"
EXT5V_FMC12V: "Header, TH, 100mil, 1x3, Gold plated, 230 mil above insulator"
FID1 FID2 FID3: "Fiducial mark.  There is nothing to buy or mount."
FMC_RX1: "Connector, Receptacle, 400-Pos (40x10), 50x50-mil Pitch, SMT"
FTDI_3P3V OR RSV "Ts ADD1": "Header, TH, 100mil, 3x1, Gold plated, 230 mil above insulator"
H3 H4: library part 1902C, "Standoff, Round, 3/16\"  x 1-3/16\"L #4-40 Aluminum"
H5 H6: "Machine Screw, Round, #4-40 x 1/4, Nylon, Philips panhead"
J1: "Header, TH, 100mil, 4x1, Gold plated, 230 mil above insulator"
L1 L27 L28 L29 L30 L31 L32 L33 L34: "0.25A Ferrite Bead, 1000 ohm @ 100MHz, SMD"
L2 L3 L4 L5 L19 L21 L22 L23: "1.5A Ferrite Bead, 330 ohm @ 100MHz, SMD"
L6 L9 L10 L13 L15 L16 L17 L18 L26: "6A Ferrite Bead, 26 ohm @ 100MHz, SMD"
L7 L14 L20 L24 L25: "3A Ferrite Bead, 120 ohm @ 100MHz, SMD"
L8: "Inductor, Shielded Drum Core, Ferrite, 3uH, 3A, 0.024 ohm, SMD"
L11: "Inductor, Shielded Drum Core, Ferrite, 7uH, 4.35A, 0.03 ohm, SMD"
L12: "Inductor, Shielded Drum Core, Superflux, 5.5uH, 10A, 0.0112 ohm, SMD"
LBL1: library part THT-14-423-10, "Thermal Transfer Printable Labels, 0.650\" W x 0.200\" H - 10,000 per roll"
LF1: "CAP, CERM, 3900pF, 25V, +/-5%, C0G/NP0, 0603"
LF3: "RES, 619 ohm, 1%, 0.1W, 0603"
LF7: "Coupled inductor, 5A, 0.01 ohm, SMD"
Logo1: library part ESD_Susceptible, "ESD Susceptible Symbol"
Logo2: library part TI_Logo, "Texas Instrument Corporate Signature"
NCO: "Header, TH, 100mil, 3x2, Gold plated, 230 mil above insulator"
OR_T0 OR_T1: "LED, Orange, SMD"
R1: "RES, 8.06k ohm, 1%, 0.063W, 0402"
R2 R10: "RES, 1.2k ohm, 5%, 0.063W, 0402"
R3 R11 R150: "RES, 1.0Meg ohm, 5%, 0.063W, 0402"
R4 R5 R6 R14 R15 R16 R105 R106 R107 R123 R130 R131: "RES, 10.0k ohm, 1%, 0.1W, 0603"
R7 R8 R9 R18 R19 R20 R21 R22 R23: "RES, 0 ohm, 5%, 0.05W, 0201"
R12: "RES, 1.33k ohm, 1%, 0.063W, 0402"
R13: "RES, 3.30k ohm, 0.1%, 0.1W, 0603"
R17: "RES, 750 ohm, 5%, 0.1W, 0603"
R24 R144: "RES, 10.0k ohm, 1%, 0.063W, 0402"
R25 R26 R29 R36 R38 R43 R44 R48 R59 R60 R61 R62 R63 R64 R145 R146 R147 R148 R149 R160 R161: "RES, 0 ohm, 5%, 0.063W, 0402"
R27 R28 R34 R35: "RES, 100 ohm, 1%, 0.063W, 0402"
R30 R153: "RES, 49.9 ohm, 1%, 0.063W, 0402"
R31 R32 R122: "RES, 1.3k ohm, 5%, 0.1W, 0603"
R33 R37: "RES, 3.3k ohm, 5%, 0.063W, 0402"
R39 R71 R80 R134: "RES, 1.0k ohm, 5%, 0.1W, 0603"
R40 R42 R73 R75 R83 R84 R92 R95: "RES, 0.002 ohm, 1%, 1W, 1206"
R41 R74: "RES, 10.7k ohm, 1%, 0.1W, 0603"
R45 R56 R112: "RES, 270 ohm, 5%, 0.1W, 0603"
R47: "RES, 2.32k ohm, 1%, 0.1W, 0603"
R49 R77: "RES, 4.64k ohm, 1%, 0.1W, 0603"
R50: library part Resistor, "RES, xxx ohm, x%, xW, [PackageReference]"
R51 R165: "RES, 51 ohm, 5%, 0.063W, 0402"
R52 R53: "RES, 10 ohm, 5%, 0.1W, 0603"
R54 R55 R57 R58 R65 R68 R69 R109 R110 R111 R113 R114 R115 R117 R118 R119 R120 R121 R124 R125 R126 R127: "RES, 100 ohm, 5%, 0.1W, 0603"
R66 R93: "RES, 1.00k ohm, 1%, 0.1W, 0603"
R67: "RES, 12.0k ohm, 1%, 0.1W, 0603"
R70: "RES, 10k ohm, 5%, 0.1W, 0603"
R72: "RES, 82.5k ohm, 1%, 0.1W, 0603"
R76: "RES, 22.1k ohm, 1%, 0.1W, 0603"
R78: "RES, 10.0 ohm, 1%, 0.1W, 0603"
R79: "RES, 732 ohm, 1%, 0.1W, 0603"
R81: "RES, 16.2k ohm, 1%, 0.1W, 0603"
R82: "RES, 7.87k ohm, 1%, 0.1W, 0603"
R85: "RES, 2.49k ohm, 1%, 0.1W, 0603"
R86 R87: "RES, 5.90k ohm, 1%, 0.1W, 0603"
R88 RR6: "RES, 4.99k ohm, 1%, 0.1W, 0603"
R89: "RES, 2.80k ohm, 1%, 0.1W, 0603"
R90: "RES, 402 ohm, 1%, 0.1W, 0603"
R91: "RES, 4.99k ohm, 1%, 0.063W, 0402"
R94: "RES, 1.0k ohm, 5%, 0.25W, 1206"
R96: "RES, 357 ohm, 1%, 0.1W, 0603"
R97 R98 R101 R102: "RES, 12.4k ohm, 1%, 0.1W, 0603"
R99 R100 R103 R132 R142 R143 R151 R152 RR7: "RES, 0 ohm, 5%, 0.1W, 0603"
R104 R116 R128 R129: "RES, 24k ohm, 5%, 0.063W, 0402"
R108: "RES, 2.2k ohm, 5%, 0.1W, 0603"
R133: "RES, 1.00k ohm, 1%, 0.063W, 0402"
R135: "RES, 2.10k ohm, 1%, 0.1W, 0603"
R136 R137 R138: "RES, 4.7k ohm, 5%, 0.1W, 0603"
R139 R140 R141: "RES, 2.0k ohm, 5%, 0.1W, 0603"
R154: "RES, 15k ohm, 5%, 0.063W, 0402"
R156 R157: "RES, 127 ohm, 1%, 0.063W, 0402"
R158 R159: "RES, 82.5 ohm, 1%, 0.063W, 0402"
R162: "RES, 107 ohm, 1%, 0.063W, 0402"
R163 R164: "RES, 2.2k ohm, 5%, 0.063W, 0402"
R166 R167: "RES, 560, 5%, 0.063 W, 0402"
S1: "SWITCH SLIDE SPST 4A PCB, TH"
SH-1V2ADC_INT_1_2 SH-1V2ADC_LDO_1_2 SH-1V9ADC_1_2 SH-1V9INT_1_2 SH-5V_12V_1_2 SH-FTDI_3P3V_1_2 SH-J2_1_2 SH-LMK_INT_1_2 SH-LMK_LDO_1_2 SH-LMX_INT_1_2 SH-LMX_LDO_1_2 SH-RSV_1_2 "SH-Ts ADD1_1_2": "Shunt, 100mil, Gold plated, Black"
SPI: "Header, TH, 100mil, 4x2, Gold plated, 230 mil above insulator"
T1: "Transformer, Multi-layer balun"
T2: "Transformer, RF, 50 ohm, 10 to 4000 MHz, SMT"
TEMP: "LED, Red, SMD"
TMST+ TMST- VIN: "Connector, SMT, End launch SMA 50 ohm"
U1: library part LMC6762AIMX, "Dual Micro-Power Rail-to-Rail Input CMOS Comparator with Push-Pull Output, 8-pin Narrow SOIC"
U2: library part ADC12X3500RFLQNOPB, "ADC12J4000RLY Ultra-Wideband RF Sampling Subsystem, RLY0068A"
U3: "Dual Remote Diode and Local Temperature Sensor with SMBus Interface and TruTherm Technology, 14-pin LLP, Pb-Free"
U4: "Integer-N/Fractional-N PLL with Integrated VCO, RHB0032E"
U5 U8: "Micropower 800mA Low Noise \"Ceramic Stable\" Adjustable Voltage Regulator for 1V to 5V Applications, 8-pin PSOP, Pb-Free"
U6: "Low-Noise Clock Jitter Cleaner with Dual Loop PLLs, NKD0064A"
U7: "3-A OUTPUT SINGLE SYNCRONOUS STEP DOWN SWITCHER WITH INTEGRATED FET(SWIFT), DDA0008B"
U9: "Dual 2A, 500kHz Wide Input Range Buck Regulator, 16-pin LLP, Pb-Free"
U10: "3.0A Low Dropout Linear Regulator with Programmable Soft-Start, RGW0020A"
U11: "3A Fast-Transient Response Adjustable Low-Dropout Linear Voltage Regulator, 5-pin TO-263 Thin, Pb-Free"
U12: "4-BIT DUAL-SUPPLY BUS TRANSCEIVER WITH CONFIGURABLE VOLTAGE TRANSLATION AND 3-STATE OUTPUTS, PW0016A"
U13: "Quad High Speed USB to Multipurpose UART/MPSSE IC"
U14: "300-mA, Low-IQ, Low-Dropout Regulator, DBV0005A"
U15: "1K, 64x16-bit, 2.5V Microwire Serial EEPROM, 8-Pin MSOP, Industrial Temperature"
U16: "64Kbit, 400kHz, 4.5V, I2C Serial EEPROM, 8-Pin SOIC 208mil, Commercial Temperature, Tape and Reel"
U17: "Divide-by-2 Divider"
U18: "IC, Single Bus Buffer Gate With 3-States Output"
USB: "MINI USB 2.0 SMT TYPE AB 5 CONTACTS R/A, SMD"
uWIRE: "Connector, 100mil Shrouded, 5x2, High-Temperature, Gold, TH"
Y1: "OSC 100.0000MHZ 3.3V +-25PPM SMD"
Y2: "Crystal, 12Mhz, 18pF, SMD"
ZZ1: library part AssemblyNoteLabel
ZZ2 ZZ3 ZZ4: library part AssemblyNote

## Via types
v1: diameter 18, hole 8, Top Layer L1 to Bottom Layer - L10, tented both sides, 1098 vias
v2: diameter 19.68, hole 7.87, Top Layer L1 to Bottom Layer - L10, 99 vias
v3: diameter 18, hole 8, Top Layer L1 to Bottom Layer - L10, tented bottom, 58 vias
v4: diameter 18, hole 8, Top Layer L1 to Bottom Layer - L10, tented top, 48 vias
v5: diameter 25.98, hole 12.99, Top Layer L1 to Bottom Layer - L10, tented top, 8 vias
v6: diameter 19.68, hole 7.87, Top Layer L1 to Bottom Layer - L10, tented top, 5 vias
v7: diameter 126, hole 106, Top Layer L1 to Bottom Layer - L10, tented top, 2 vias

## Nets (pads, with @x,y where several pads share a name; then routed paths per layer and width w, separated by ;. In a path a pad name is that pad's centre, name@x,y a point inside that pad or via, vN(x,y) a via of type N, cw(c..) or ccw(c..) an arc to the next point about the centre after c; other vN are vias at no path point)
1P8V_USB: 1P8USB.1 C133.1 C134.1 C136.1 C200.1 C212.2 U13.12 U13.37 U13.49 U13.64 | length 608
  Top Layer L1 w10: v1(2562.5,419.1) U13.12@2616.97,419.1 ; v1(2671,760.97) 2687.83,744.14 U13.64@2687.83,706.5 ; U13.49@2983.11,706.5 2983.11,751.13 v1(2992.95,760.97) ; v1(2999.51,419.1) U13.37@3053.98,419.1 3096.83,419.1 C134.1@3108.45,407.49 3110.22,409.26 v1(3121,409.26)
  Top Layer L1 w16.5: C133.1@2541.44,419.1 v1(2562.5,419.1) ; v1(2671,760.97) C136.1@2671,782.03
  Top Layer L1 w24: v1(2992.95,760.97) 2992.95,785.96 C200.1@2996.7,789.7
  Bottom Layer - L10 w24: C212.2@2976,860.09 C212.2@2990.09,846 ; v1(2992.95,760.97) C212.2@2992.95,843.13 ; C212.2@2992.95,819 1P8USB.1@3125,819
3P3V_FTDI: C118.1 C119.1 C129.1 C131.1 C132.1 C205.1 C213.1 C214.1 FTDI_3P3V.2 L24.1 L25.1 R66.2 R105.2 R106.2 R107.2 U12.1 U12.2 U12.8 U12.16 U13.20 U13.31 U13.42 U13.50 U13.56 U15.8 U18.5 USB_PWR.1 | length 2260.4
  Top Layer L1 w8: U12.2@3876.76,429.5 3842.79,429.5 v1(3830,442.3) 3842.8,455.1 U12.1@3876.76,455.1
  Top Layer L1 w10: U13.20@2746.89,269.5 2746.89,224.87 C118.1@2756.73,215.03 ; U13.56@2845.31,706.5 v1(2845.31,760.97) ; v1(2953.58,760.97) 2963.42,751.13 U13.50@2963.42,706.5 ; v1(2963.43,215.03) U13.31@2963.42,269.5 ; v1(2999.51,517.53) U13.42@3053.98,517.53 3096.83,517.53 3100.14,520.84 3114.47,520.84 v1(3121,527.37)
  Top Layer L1 w13: v1(3876.76,250) U12.8@3876.76,275.96 ; U12.16@4097.24,455.1 C129.1@4097.24,502.06
  Top Layer L1 w16: v1(3121,527.37) 3124.45,530.82 C131.1@3124.45,545.43
  Top Layer L1 w16.5: R107.2@2706.2,842.56 v1(2771,842.56) ; C118.1@2756.73,215.03 2756.73,204.27 v1(2771,190) ; v1(2845.31,760.97) C132.1@2845.31,781.24 ; v1(2953.58,760.97) C214.1@2953.58,781.24 ; v1(2963.43,215.03) 2968.43,210.03 C119.1@2984.48,210.03
  Top Layer L1 w24: C129.1@4097.24,502.06 v1(4097.24,530.79)
  Signals - L3 w24: v1(3121,527.37) 3172.63,527.37 3230,470 3433,470 3466,503 3506,503 3519,490 3782.3,490 v1(3830,442.3)
  Bottom Layer - L10 w16.5: R105.2@2817.32,762.56 2818.91,760.97 v1(2845.31,760.97) ; U18.5@2902.07,430.85 2961.59,430.85 C213.1@2966,435.25 v1(2966,460) ; v1(2999.51,517.53) 2982.68,517.53 U15.8@2982.68,528.61 3037.17,528.61 C205.1@3048,539.44
  Bottom Layer - L10 w24: L24.1@2690.5,491 v1(2730,491) ; v1(3830,442.3) 3876.76,442.3 ; v1(3876.76,250) 3876.76,442.3 ; v1(4097.24,530.79) 4008.75,442.3 3876.76,442.3
  other v1: 2480.91,304.73 2480.91,351.73 2598.56,709.56
3P3V_RX: 3P3RX.1 R132.1 | length 105.4
  Top Layer L1 w25: 3P3RX.1@4893,515 R132.1@4998.44,515
3P3V_USB: C138.1 C210.1 FTDI_3P3V.3 L26.2 | length 146.8
  Bottom Layer - L10 w16.5: v1(83.74,839) 83.74,722.26 92.46,713.54 v1(110.24,713.54)
  other v1: 83.74,775.86
3P3VAUX: C143.1 FMC_RX1.D32 J1.4 U16.8 | length 1706.1
  Top Layer L1 w18: J1.4@3952,540 4034,622 C143.1@4074.14,622 U16.8@4074.14,690
  Signals - L8 w18: v1(4074.14,665) 4174.14,765 5444,765 v3(5469,740)
  Bottom Layer - L10 w18: v3(5469,740) FMC_RX1.D32@5494,765
5P0_12P0V_INT: C94.1 C145.1 C146.1 C147.1 C167.1 C173.1 C184.1 C220.2 C221.2 C222.2 C223.2 C225.2 C226.2 C227.2 C261.1 EXT5V_FMC12V.2 R70.1 R78.1 R79.2 R94.2 U7.8 U9.11 U9.12 U9.13 U9.14 | length 307.8
  Top Layer L1 w10: v1@3825.47,1396 U9.11@3825.47,1429.51 ; 3845.16,1396 U9.12@3845.16,1429.51 ; 3864.84,1396 U9.13@3864.84,1429.51 ; v1@3884.53,1396 U9.14@3884.53,1429.51
  Top Layer L1 w18: v1(3829.47,1340) v1(3880.53,1340)
  Bottom Layer - L10 w8: 3872.77,1403.76 v1(3880.53,1396)
  Bottom Layer - L10 w18: v1@4691,1289.56 4726.19,1254.37 R70.1@4726.19,1192.41
  other v1: 4746,235.85 5219,590 3492.69,990 3407.69,1090 4106.31,1090 4573.69,1090 4614,1290 4650,1290 4691,1290 3855,1340 3829.47,1396 3855,1396 3879,1740 3407.69,1790 4106.31,1790 4361.69,1790 5219,1790 3449.68,2511.44
12P0V_RX: C94.2 EXT5V_FMC12V.3 FMC_RX1.C35 FMC_RX1.C37 | length 176.8
  Bottom Layer - L10 w18: v1(5519,490) FMC_RX1.C37@5544,515 ; v3(5569,490) FMC_RX1.C37@5544,515 ; v3(5569,540) FMC_RX1.C37@5544,515 ; v3(5569,590) FMC_RX1.C35@5544,615 v3(5569,640)
  other v1: 5219,540
ADC_OR_T0: D2.2 FMC_RX1.G27 OR.3 U2.25 | length 5353.7
  Signals - L3 w4: v1(1140.04,1710.8) 1167.24,1738 1209,1738 1455.5,1984.5 OR.3@1455.5,2015 1505.5,2065 1688,2065 1710,2043 1710,1993 1734,1969 1734,1542 1912,1364 2263,1364 2431,1196 2504,1196 v1(2535,1165)
  Signals - L6 w4: v1(2535,1165) 2585,1215 4999,1215 5149,1065 5344,1065 v3(5369,1040)
  Bottom Layer - L10 w8: v1(1140.04,1710.8) 1143.7,1707.14 U2.25@1143.7,1532.91 ; FMC_RX1.G27@5344,1015 v3(5369,1040)
ADC_OR_T1: D4.2 FMC_RX1.D26 OR.1 U2.26 | length 5368.5
  Signals - L3 w4: v1(1167.05,1710.8) 1221.8,1710.8 1426,1915 1555.5,1915 OR.1@1655.5,2015 1698,1972.5 1698,1529 1913,1314 2260,1314 2434,1140 2510,1140 v1(2535,1115)
  Signals - L6 w4: v1(2535,1115) 2585,1165 4999,1165 5149,1015 5444,1015 v3(5469,1040)
  Bottom Layer - L10 w8: U2.26@1163.39,1532.91 1163.39,1707.14 v1(1167.05,1710.8) ; v3(5469,1040) FMC_RX1.D26@5494,1065
CLK0_N: R63.1 U6.2 | length 101.6
  Top Layer L1 w8: U6.2@995.61,1973.77 995.61,1961.77 993.76,1959.93 993.76,1885.68 R63.1@1002.76,1876.68
CLK0_P: R64.1 U6.1 | length 101.6
  Top Layer L1 w8: R64.1@968.76,1876.68 977.76,1885.68 977.76,1959.93 975.92,1961.77 U6.1@975.92,1973.77
CLK3_N: R61.1 U6.14 | length 101.6
  Top Layer L1 w8: U6.14@1231.83,1973.77 1231.83,1961.77 1229.99,1959.93 1229.99,1885.68 R61.1@1238.98,1876.69
CLK3_P: R62.1 U6.13 | length 101.6
  Top Layer L1 w8: R62.1@1204.98,1876.69 1213.98,1885.68 1213.98,1959.93 1212.14,1961.77 U6.13@1212.14,1973.77
CLK4_N: R59.1 U6.25 | length 101.6
  Top Layer L1 w8: U6.25@1296.79,2156.84 1308.79,2156.84 1310.63,2155 1384.87,2155 R59.1@1393.87,2164
CLK4_P: R60.1 U6.24 | length 101.6
  Top Layer L1 w8: U6.24@1296.79,2137.16 1308.79,2137.16 1310.63,2139 1384.87,2139 R60.1@1393.87,2130
CLK10_N: R160.1 R167.2 U6.55 | length 150.5
  Top Layer L1 w8: R160.1@816.47,2193.37 850.56,2193.37 R167.2@853.24,2190.68 864.93,2202.37 872.05,2202.37 896.05,2178.37 936.49,2178.37 938.33,2176.53 U6.55@950.33,2176.53
CLK10_P: R161.1 R167.1 U6.54 | length 150.5
  Top Layer L1 w8: R161.1@816.47,2227.37 850.56,2227.37 R167.1@853.24,2230.05 864.93,2218.37 878.68,2218.37 902.68,2194.37 936.49,2194.37 938.33,2196.21 U6.54@950.33,2196.21
CLK11_N: R43.1 R166.2 U6.57 | length 150.5
  Top Layer L1 w8: R43.1@816.47,2106 850.56,2106 R166.2@853.24,2103.31 864.93,2115 890.68,2115 914.68,2139 936.49,2139 938.33,2137.16 U6.57@950.33,2137.16
CLK11_P: R44.1 R166.1 U6.56 | length 150.5
  Top Layer L1 w8: R44.1@816.47,2140 850.56,2140 R166.1@853.24,2142.68 864.93,2131 884.05,2131 908.05,2155 936.49,2155 938.33,2156.84 U6.56@950.33,2156.84
CLKIN1_N: C112.1 C123.1 U6.35 | length 101.6
  Top Layer L1 w8: v4(1224.67,2417.32) 1233.67,2408.32 1233.67,2334.07 1231.83,2332.23 U6.35@1231.83,2320.23
CLKIN1_P: C113.1 C114.2 U6.34 | length 101.6
  Top Layer L1 w8: U6.34@1251.51,2320.23 1251.51,2332.23 1249.67,2334.07 1249.67,2408.32 v4(1258.67,2417.32)
D0_N: C9.1 FMC_RX1.C6 | length 4573.1
  Signals - L8 w4: v1(1277.84,1695.8) 1287.34,1705.3 1287.34,1747.83 1408.5,1869 5386.69,1869 5390,1872.31 5390,2057.31 5401.69,2069 5498,2069 v3(5519,2090)
  Bottom Layer - L10 w8: v3(5519,2090) FMC_RX1.C6@5544,2065
D0_P: C7.1 FMC_RX1.C7 | length 4573.3
  Signals - L8 w4: v1(1304.84,1695.8) 1295.34,1705.3 1295.34,1744.52 1411.82,1861 5390,1861 5398,1869 5398,2054 5405,2061 5514,2061 5524,2051 5524,2045 v3(5519,2040)
  Bottom Layer - L10 w8: v3(5519,2040) FMC_RX1.C7@5544,2015
D1_N: C12.1 FMC_RX1.A2 | length 4715.6
  Signals - L8 w4: v1(1609.19,1501.14) 1618.69,1491.64 1650.31,1491.64 1727.68,1569 5236.69,1569 5240,1572.31 5240,1811 5248,1819 5436.69,1819 5440,1822.31 5440,1961 5448,1969 5533,1969 5540,1976 5540,2207.31 5551.69,2219 5598,2219 v3(5619,2240)
  Bottom Layer - L10 w8: v3(5619,2240) FMC_RX1.A2@5644,2265
D1_P: C10.1 FMC_RX1.A3 | length 4715.6
  Signals - L8 w4: v1(1609.19,1474.14) 1618.69,1483.64 1653.63,1483.64 1730.99,1561 5240,1561 5248,1569 5248,1807.69 5251.31,1811 5440,1811 5448,1819 5448,1957.69 5451.31,1961 5536.31,1961 5548,1972.69 5548,2204 5555,2211 5598,2211 v3(5619,2190)
  Bottom Layer - L10 w8: v3(5619,2190) FMC_RX1.A3@5644,2215
D2_N: C14.1 FMC_RX1.A6 | length 4709.4
  Signals - L8 w4: v1(1519.19,1442.08) 1528.69,1432.58 1650.31,1432.58 1736.73,1519 5286.69,1519 5290,1522.31 5290,1761 5298,1769 5486.69,1769 5490,1772.31 5490,1911 5498,1919 5583,1919 5590,1926 5590,2007.31 5601.69,2019 5648,2019 v3(5669,2040)
  Bottom Layer - L10 w8: FMC_RX1.A6@5644,2065 v3(5669,2040)
D2_P: C13.1 FMC_RX1.A7 | length 4709.4
  Signals - L8 w4: v1(1519.19,1415.08) 1528.69,1424.58 1653.63,1424.58 1740.05,1511 5290,1511 5298,1519 5298,1757.69 5301.31,1761 5490,1761 5498,1769 5498,1907.69 5501.31,1911 5586.31,1911 5598,1922.69 5598,2004 5605,2011 5648,2011 v3(5669,1990)
  Bottom Layer - L10 w8: FMC_RX1.A7@5644,2015 v3(5669,1990)
D3_N: C17.1 FMC_RX1.A10 | length 4484.1
  Signals - L8 w4: v1(1609.19,1383.03) 1618.69,1373.53 1650.31,1373.53 1745.79,1469 5336.69,1469 5340,1472.31 5340,1711 5348,1719 5536.69,1719 5540,1722.31 5540,1861 5548,1869 5598,1869 v3(5619,1890)
  Bottom Layer - L10 w8: v3(5619,1890) FMC_RX1.A10@5644,1865
D3_P: C15.1 FMC_RX1.A11 | length 4484.1
  Signals - L8 w4: v1(1609.19,1356.03) 1618.69,1365.53 1653.63,1365.53 1749.1,1461 5340,1461 5348,1469 5348,1707.69 5351.31,1711 5540,1711 5548,1719 5548,1857.69 5551.31,1861 5598,1861 v3(5619,1840)
  Bottom Layer - L10 w8: v3(5619,1840) FMC_RX1.A11@5644,1815
D4_N: C21.1 FMC_RX1.A14 | length 4463.8
  Signals - L8 w4: v1(1519.19,1323.97) 1528.69,1314.47 1650.31,1314.47 1704.84,1369 5386.69,1369 5390,1372.31 5390,1661 5398,1669 5598,1669 v3(5619,1690)
  Bottom Layer - L10 w8: v3(5619,1690) FMC_RX1.A14@5644,1665
D4_P: C20.1 FMC_RX1.A15 | length 4463.8
  Signals - L8 w4: v1(1519.19,1296.97) 1528.69,1306.47 1653.63,1306.47 1708.16,1361 5390,1361 5398,1369 5398,1657.69 5401.31,1661 5598,1661 v3(5619,1640)
  Bottom Layer - L10 w8: v3(5619,1640) FMC_RX1.A15@5644,1615
D5_N: C23.1 FMC_RX1.A18 | length 4566.6
  Signals - L8 w4: v1(1609.19,1264.92) 1618.69,1255.42 1650.31,1255.42 1713.9,1319 5436.69,1319 5440,1322.31 5440,1611 5448,1619 5586.31,1619 5598,1607.31 5598,1476 5605,1469 5648,1469 v3(5669,1490)
  Bottom Layer - L10 w8: FMC_RX1.A18@5644,1465 v3(5669,1490)
D5_P: C22.1 FMC_RX1.A19 | length 4566.6
  Signals - L8 w4: v1(1609.19,1237.92) 1618.69,1247.42 1653.63,1247.42 1717.21,1311 5440,1311 5448,1319 5448,1607.69 5451.31,1611 5583,1611 5590,1604 5590,1472.69 5601.69,1461 5648,1461 v3(5669,1440)
  Bottom Layer - L10 w8: FMC_RX1.A19@5644,1415 v3(5669,1440)
D6_N: C28.1 FMC_RX1.B16 | length 4421.3
  Signals - L8 w4: v1(1519.19,1205.86) 1528.69,1196.36 1650.31,1196.36 1722.95,1269 5486.69,1269 5490,1272.31 5490,1561 5498,1569 5548,1569 v3(5569,1590)
  Bottom Layer - L10 w8: v3(5569,1590) FMC_RX1.B16@5594,1565
D6_P: C26.1 FMC_RX1.B17 | length 4421.3
  Signals - L8 w4: v1(1519.19,1178.86) 1528.69,1188.36 1653.63,1188.36 1726.27,1261 5490,1261 5498,1269 5498,1557.69 5501.31,1561 5548,1561 v3(5569,1540)
  Bottom Layer - L10 w8: v3(5569,1540) FMC_RX1.B17@5594,1515
D7_N: C31.1 FMC_RX1.B12 | length 5052
  Signals - L8 w4: v1(1304.84,984.2) 1304.84,999.89 1316.15,1011.2 5295.86,1011.2 5698,1413.34 5698,1757.31 5686.31,1769 5640,1769 v3(5619,1790)
  Bottom Layer - L10 w8: FMC_RX1.B12@5594,1765 v3(5619,1790)
D7_P: C29.1 FMC_RX1.B13 | length 5051.9
  Signals - L8 w4: v1(1277.84,984.2) 1312.84,1019.2 5292.54,1019.2 5690,1416.66 5690,1754 5683,1761 5631,1761 5619,1749 v3(5619,1740)
  Bottom Layer - L10 w8: FMC_RX1.B13@5594,1715 v3(5619,1740)
DEV_CLK_N: C263.2 R160.2 | length 898.6
  Top Layer L1 w4: C263.2@833.57,1507.44 v1(833.57,1529.49)
  Signals - L8 w4: v1(777.1,2193.37) 786.22,2202.49 786.22,2208 781.86,2212.37 773.41,2212.37 752,2190.96 752,1491.01 771.06,1471.95 776.03,1471.95 v1(833.57,1529.49)
DEV_CLK_P: C262.2 R161.2 | length 898.7
  Top Layer L1 w8: v1(833.57,1406.41) C262.2@833.57,1428.47
  Signals - L8 w4: v1(777.1,2227.37) 744,2194.27 744,1487.7 767.75,1463.95 776.03,1463.95 v1(833.57,1406.41)
DEVCLK_N: C33.1 C36.1 C93.1 C263.1 U2.16 | length 139.9
  Bottom Layer - L10 w8: v1(833.57,1481.45) 839.07,1475.95 968.63,1475.95 U2.16@970.47,1477.8
DEVCLK_P: C30.1 C32.1 C92.1 C262.1 U2.15 | length 139.9
  Bottom Layer - L10 w8: v1(833.57,1454.45) 839.07,1459.95 968.63,1459.95 U2.15@970.47,1458.11
DEVCLKARX_N: FMC_RX1.D5 R60.2 | length 4098.5
  Signals - L8 w4: v1(1433.24,2130) 1446.25,2143 1471.06,2143 1503.06,2111 5448,2111 v3(5469,2090)
  Bottom Layer - L10 w8: v3(5469,2090) FMC_RX1.D5@5494,2115
DEVCLKARX_P: FMC_RX1.D4 R59.2 | length 4098.4
  Signals - L8 w4: v1(1433.25,2164) 1446.24,2151 1474.37,2151 1506.38,2119 5448,2119 v3(5469,2140)
  Bottom Layer - L10 w8: v3(5469,2140) FMC_RX1.D4@5494,2165
DEVCLKBRX_N: FMC_RX1.G7 R63.2 | length 4494.7
  Signals - L8 w4: v1(1002.76,1837.31) 989.76,1850.32 989.76,1858.13 995.95,1864.32 1161.32,1864.32 1258,1961 5236.31,1961 5248,1972.69 5248,2004 5255,2011 5314,2011 5324,2001 5324,1995 v3(5319,1990)
  Bottom Layer - L10 w8: v3(5319,1990) FMC_RX1.G7@5344,2015
DEVCLKBRX_P: FMC_RX1.G6 R64.2 | length 4494.4
  Signals - L8 w4: v1(968.76,1837.32) 981.76,1850.32 981.76,1861.45 992.63,1872.32 1158,1872.32 1254.69,1969 5233,1969 5240,1976 5240,2007.31 5251.69,2019 5298,2019 v3(5319,2040)
  Bottom Layer - L10 w8: v3(5319,2040) FMC_RX1.G6@5344,2065
EE_ADDR0_RX: FMC_RX1.C34 U16.1 | length 1233.2
  Top Layer L1 w8: U16.1@4341.86,690 v1(4397.16,690)
  Signals - L3 w4: v1(4397.16,690) 4422.16,665 5494,665 v3(5519,690)
  Bottom Layer - L10 w8: v3(5519,690) FMC_RX1.C34@5544,665
EE_ADDR1_RX: FMC_RX1.D35 U16.2 | length 1325.6
  Top Layer L1 w8: U16.2@4341.86,740 v1(4397.16,740)
  Signals - L3 w4: v1(4397.16,740) 4422.17,715 5531,715 5544,702 5544,665 v3(5519,640)
  Bottom Layer - L10 w8: FMC_RX1.D35@5494,615 v3(5519,640)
